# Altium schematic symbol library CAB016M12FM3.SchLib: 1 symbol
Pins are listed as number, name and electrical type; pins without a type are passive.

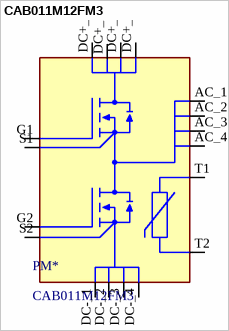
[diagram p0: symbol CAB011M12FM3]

## CAB011M12FM3
designator PM*
Schematic Symbol for Wolfpack FM Half-Bridge 11mO module
footprint CAB016M12FM3 (CAB016M12FM3 Footprint)
pins: AC_1, AC_2, AC_3, AC_4, DC+_1, DC+_2, DC+_3, DC+_4, DC-_1, DC-_2, DC-_3, DC-_4, G1, G2, S1, S2, T1, T2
